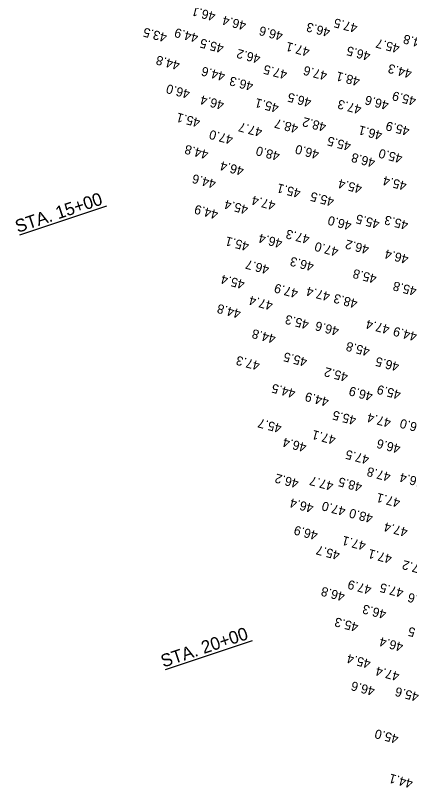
# Model space of a CAD drawing. Extents: x 944701 to 948101, y 637871 to 642271.
# Drawn here: x 945690 to 946120, y 639759 to 640601 of the extents above; entities that cross this region are included whole.
import ezdxf

# ---------------------------------------------------------------- set-up
doc = ezdxf.new("R2010")
doc.units = 0
doc.layers.add('V-ALGN-TEXT', color=7, linetype='Continuous')
doc.layers.add('V-TOPO-SOUN', color=7, linetype='Continuous')

msp = doc.modelspace()

# ---------------------------------------------------------------- linework, layer by layer
at = {"layer": 'V-ALGN-TEXT'}
for p, q in [((945694.71, 640361.31), (945789.52, 640393.1)), ((945853.67, 639887.25), (945948.48, 639919.05))]:
    msp.add_line(p, q, dxfattribs=at)

# ---------------------------------------------------------------- texts
for s, p in [('STA. 15+00', (945692.23, 640363.42)), ('STA. 20+00', (945851.2, 639889.36))]:
    msp.add_text(s, height=13.92, rotation=18.5381, dxfattribs=at).set_placement(p)
at = {"layer": 'V-TOPO-SOUN'}
for s, p in [('46.1 ', (945908.83, 640603.74)), ('46.4 ', (945942.37, 640593.78)), ('47.5 ', (946063.91, 640591)), ('43.5 ', (945855.88, 640580.81)), ('46.6 ', (945982.47, 640582.42)), ('46.3 ', (946034.11, 640586.43)), ('44.9 ', (945890.08, 640580.32)), ('44.8 ', (946139.7, 640573.34)), ('45.5 ', (945917.81, 640568.87)), ('47.1 ', (946011.7, 640565.17)), ('45.7 ', (946109.9, 640568.77)), ('46.2 ', (945957.91, 640557.51)), ('46.5 ', (946077.95, 640560.54)), ('44.8 ', (945869.92, 640550.35)), ('47.5 ', (945987.14, 640540.25)), ('47.6 ', (946030.8, 640539.11)), ('44.3 ', (946123.19, 640541.21)), ('44.6 ', (945919.48, 640538.32)), ('48.1 ', (946066.5, 640532.81)), ('46.3 ', (945950.12, 640527.63)), ('46.0 ', (945881.05, 640519.14)), ('46.4 ', (945918.24, 640507.03)), ('46.5 ', (946013.54, 640509.88)), ('46.6 ', (946097.97, 640506.84)), ('45.9 ', (946127.77, 640511.41)), ('45.1 ', (945977.93, 640503.81)), ('47.3 ', (946068.17, 640502.26)), ('45.1 ', (945892.18, 640487.93)), ('48.7 ', (945999.19, 640481.4)), ('48.2 ', (946029.74, 640483.07)), ('47.7 ', (945959.93, 640477.49)), ('46.1 ', (946090.92, 640474.04)), ('45.9 ', (946120.72, 640478.62)), ('47.0 ', (945927.97, 640469.26)), ('45.5 ', (946056.81, 640462.16)), ('44.8 ', (945901.16, 640453.06)), ('48.0 ', (945979.03, 640451.43)), ('46.0 ', (946021.95, 640453.18)), ('45.0 ', (946112.93, 640448.73)), ('46.8 ', (946083.13, 640444.16)), ('46.4 ', (945939.85, 640435.14)), ('44.6 ', (945909.39, 640421.11)), ('45.4 ', (946068.78, 640415.68)), ('45.4 ', (946117.51, 640418.93)), ('45.1 ', (946001.87, 640410.84)), ('47.4 ', (945974.31, 640397.55)), ('45.5 ', (946038.32, 640401.64)), ('44.9 ', (945911.81, 640387.65)), ('45.4 ', (945944.51, 640392.98)), ('46.0 ', (946057.42, 640375.58)), ('45.5 ', (946087.97, 640377.25)), ('45.3 ', (946119.26, 640376.01)), ('46.4 ', (945981.88, 640356.13)), ('47.3 ', (946011.68, 640360.7)), ('45.1 ', (945945.52, 640352.96)), ('47.0 ', (946043.07, 640347.1)), ('46.2 ', (946076.52, 640349.52)), ('46.4 ', (946119.52, 640338.91)), ('46.3 ', (946016.26, 640330.9)), ('46.7 ', (945967.53, 640327.65)), ('45.4 ', (945940.72, 640311.45)), ('45.8 ', (946084.75, 640317.56)), ('45.8 ', (946128.5, 640304.04)), ('47.9 ', (945999, 640301.68)), ('47.4 ', (946033.95, 640298.28)), ('47.4 ', (945971.44, 640288.39)), ('48.3 ', (946063.84, 640290.49)), ('44.8 ', (945936.58, 640279.41)), ('45.3 ', (946010.88, 640267.56)), ('47.4 ', (946098.96, 640262.36)), ('46.6 ', (946043.67, 640260.52)), ('44.9 ', (946128.85, 640254.57)), ('44.8 ', (945974.61, 640252.03)), ('45.8 ', (946077.3, 640238.2)), ('47.3 ', (945957.35, 640222.8)), ('45.5 ', (946008.98, 640226.8)), ('46.5 ', (946109.43, 640221.69)), ('45.2 ', (946053.49, 640210.38)), ('44.5 ', (945996.13, 640192.51)), ('46.9 ', (946080.55, 640189.47)), ('45.9 ', (946111.1, 640191.14)), ('44.9 ', (946032.57, 640183.31)), ('45.5 ', (946062.55, 640163.15)), ('47.4 ', (946100.4, 640160.5)), ('45.7 ', (945981.12, 640154.57)), ('46.0 ', (946136.1, 640154.21)), ('47.1 ', (946040.14, 640141.89)), ('46.4 ', (946008.18, 640133.66)), ('46.6 ', (946110.79, 640132.2)), ('47.5 ', (946076.67, 640120.32)), ('47.8 ', (946100.09, 640101.56)), ('46.2 ', (945999.73, 640094.31)), ('46.4 ', (946135.79, 640095.27)), ('47.7 ', (946037.58, 640091.67)), ('48.5 ', (946068.88, 640090.43)), ('46.4 ', (946015.93, 640067.5)), ('47.1 ', (946110.48, 640073.26)), ('47.0 ', (946050.88, 640064.11)), ('48.0 ', (946080.76, 640056.31)), ('46.9 ', (946020.5, 640037.7)), ('47.4 ', (946118.7, 640041.3)), ('47.1 ', (946072.97, 640026.43)), ('45.7 ', (946044.66, 640016.04)), ('47.1 ', (946101.45, 640012.08)), ('47.2 ', (946138.64, 639999.97)), ('47.9 ', (946079.13, 639978.45)), ('47.5 ', (946114.08, 639975.06)), ('46.8 ', (946050.07, 639970.97)), ('46.6 ', (946144.71, 639964.36)), ('46.3 ', (946095.32, 639951.64)), ('45.3 ', (946064.86, 639937.6)), ('47.5 ', (946144.97, 639927.25)), ('46.4 ', (946113.76, 639916.12)), ('45.4 ', (946078.24, 639897.68)), ('47.4 ', (946109.62, 639884.07)), ('46.6 ', (946082.82, 639867.87)), ('45.6 ', (946130.88, 639861.66)), ('45.0 ', (946108.65, 639815.67)), ('44.1 ', (946124.27, 639767.03))]:
    msp.add_text(s, height=9.996, rotation=165, dxfattribs=at).set_placement(p)

doc.saveas('drawing.dxf')
